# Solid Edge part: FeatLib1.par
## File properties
Author: Mac
Template: Normal.par
Last saved by: Mac
Revision: 1
Application: Solid Edge
Material: Stainless steel
Face Style: Steel
Fill Style: ANSI32(Steel)
Virtual Style: Stainless steel
Coef. of Thermal Exp: 1.6e-05
Thermal Conductivity: 17.0
Specific Heat: 502.0
Modulus of Elasticity: 193053196000.0
Poission's Ratio: 0.29
Yield Stress: 310264065.0
Ultimate Stress: 641212401.0
Elongation: 0.0
Accuracy: 0,990
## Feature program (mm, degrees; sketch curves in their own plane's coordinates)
extrude "unnamed Protrusion 1" add finite 10
sketch for "unnamed Protrusion 2" #1 plane through (-10, 5, 10) normal (0, 0, 1) x-axis (1, 0, 0)
sketch for "unnamed Protrusion 2" #2 plane through (-10, 5, 10) normal (0, 0, 1) x-axis (1, 0, 0)
sketch for "unnamed Protrusion 2" #3 plane through (-10, 5, 10) normal (0, 0, 1) x-axis (1, 0, 0)
extrude "unnamed Protrusion 2" add finite 1 along +normal
sketch for "unnamed Cutout 1" #1 plane through (-0.6921, 7.9454, 11) normal (0, 0, 1) x-axis (0, 1, 0)
sketch for "unnamed Cutout 1" #2 plane through (-0.6921, 7.9454, 11) normal (0, 0, 1) x-axis (0, 1, 0)
extrude "unnamed Cutout 1" cut finite 10 along -normal
thinwall "unnamed Thinwall 1"
sketch for "unnamed Cutout 2" plane through (-0.6921, 9.2965, 11) normal (0, 0, 1) x-axis (0, 1, 0)
extrude "unnamed Cutout 2" cut through along -normal
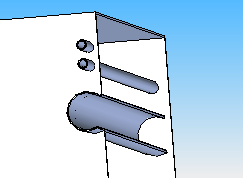
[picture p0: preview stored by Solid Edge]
